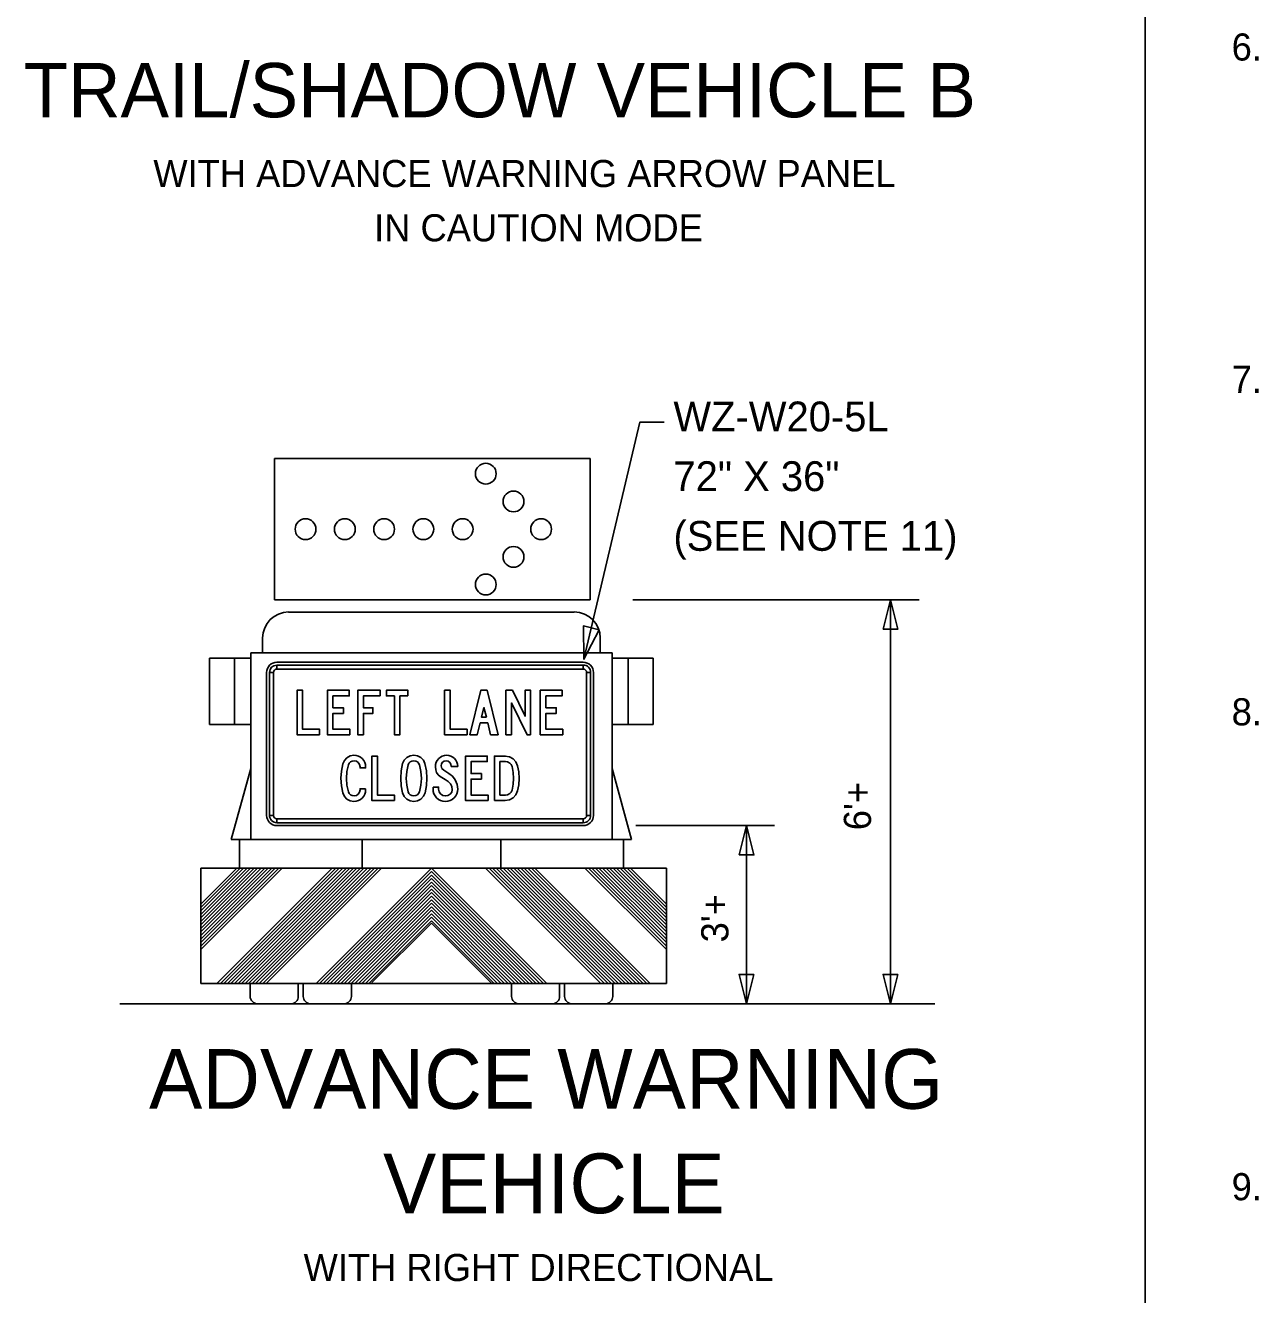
# Model space of a CAD drawing. Extents: x 1374027 to 1374537, y 380415 to 381405.
# Drawn here: x 1374116.56 to 1374143.82, y 381323.05 to 381351.11 of the extents above; entities that cross this region are included whole.
import ezdxf

# ---------------------------------------------------------------- set-up
doc = ezdxf.new("R2010")
doc.units = 0
doc.layers.add('Working Level 1', color=7, linetype='Continuous')

msp = doc.modelspace()

# ---------------------------------------------------------------- linework, layer by layer
at = {"layer": 'Working Level 1'}
for p, q in [((1374141.313, 381402.674), (1374141.313, 381297.674)), ((1374122.066, 381341.535), (1374129.043, 381341.535)), ((1374122.066, 381338.407), (1374122.066, 381341.535)), ((1374129.043, 381338.407), (1374129.043, 381341.535)), ((1374122.066, 381338.407), (1374129.043, 381338.407)), ((1374129.989, 381338.407), (1374136.317, 381338.407)), ((1374135.68, 381329.476), (1374135.68, 381338.407)), ((1374135.68, 381338.407), (1374135.68, 381337.883)), ((1374122.38, 381338.139), (1374128.694, 381338.139)), ((1374121.806, 381337.236), (1374121.806, 381337.566)), ((1374129.268, 381337.236), (1374129.268, 381337.566)), ((1374120.635, 381337.119), (1374121.546, 381337.119)), ((1374120.635, 381335.653), (1374120.635, 381337.119)), ((1374121.187, 381335.653), (1374121.187, 381337.119)), ((1374121.546, 381333.109), (1374121.546, 381337.236)), ((1374121.546, 381337.236), (1374129.529, 381337.236)), ((1374128.892, 381337.029), (1374122.12, 381337.029)), ((1374129.529, 381333.109), (1374129.529, 381337.236)), ((1374130.439, 381337.119), (1374129.529, 381337.119)), ((1374129.888, 381335.653), (1374129.888, 381337.119)), ((1374130.439, 381335.653), (1374130.439, 381337.119)), ((1374121.895, 381336.803), (1374121.895, 381333.643)), ((1374121.957, 381336.803), (1374122.045, 381336.803)), ((1374122.12, 381336.878), (1374122.12, 381336.966)), ((1374128.892, 381336.966), (1374128.892, 381336.878)), ((1374128.967, 381336.803), (1374129.055, 381336.803)), ((1374129.117, 381333.643), (1374129.117, 381336.803)), ((1374120.635, 381335.653), (1374121.546, 381335.653)), ((1374130.439, 381335.653), (1374129.529, 381335.653)), ((1374121.546, 381334.681), (1374121.114, 381333.109)), ((1374129.529, 381334.681), (1374129.96, 381333.109)), ((1374122.045, 381333.643), (1374121.957, 381333.643)), ((1374129.055, 381333.643), (1374128.967, 381333.643)), ((1374122.12, 381333.48), (1374122.12, 381333.568)), ((1374122.12, 381333.417), (1374128.892, 381333.417)), ((1374128.892, 381333.568), (1374128.892, 381333.48)), ((1374130.055, 381333.417), (1374133.116, 381333.417)), ((1374132.499, 381329.476), (1374132.499, 381333.417)), ((1374132.499, 381333.417), (1374132.499, 381332.885)), ((1374121.114, 381333.109), (1374129.96, 381333.109)), ((1374121.293, 381332.479), (1374121.293, 381333.109)), ((1374124.005, 381332.479), (1374124.005, 381333.098)), ((1374127.069, 381332.479), (1374127.069, 381333.098)), ((1374129.781, 381332.479), (1374129.781, 381333.109)), ((1374120.437, 381332.479), (1374130.731, 381332.479)), ((1374120.437, 381332.479), (1374130.731, 381332.479)), ((1374120.437, 381332.479), (1374130.731, 381332.479)), ((1374120.437, 381332.479), (1374130.731, 381332.479)), ((1374120.437, 381329.929), (1374120.437, 381332.479)), ((1374120.437, 381331.681), (1374121.235, 381332.479)), ((1374120.437, 381330.753), (1374122.162, 381332.479)), ((1374120.437, 381330.831), (1374122.084, 381332.479)), ((1374120.437, 381330.909), (1374122.006, 381332.479)), ((1374120.437, 381330.986), (1374121.929, 381332.479)), ((1374120.437, 381331.065), (1374121.851, 381332.479)), ((1374120.437, 381331.143), (1374121.773, 381332.479)), ((1374120.437, 381331.22), (1374121.696, 381332.479)), ((1374120.437, 381331.298), (1374121.618, 381332.479)), ((1374120.437, 381331.376), (1374121.54, 381332.479)), ((1374120.437, 381331.454), (1374121.462, 381332.479)), ((1374120.437, 381331.531), (1374121.385, 381332.479)), ((1374120.437, 381331.609), (1374121.307, 381332.479)), ((1374120.437, 381330.676), (1374122.238, 381332.477)), ((1374120.796, 381329.929), (1374123.345, 381332.479)), ((1374120.873, 381329.929), (1374123.423, 381332.479)), ((1374120.951, 381329.929), (1374123.501, 381332.479)), ((1374121.029, 381329.929), (1374123.579, 381332.479)), ((1374121.106, 381329.929), (1374123.656, 381332.479)), ((1374121.185, 381329.929), (1374123.734, 381332.479)), ((1374121.263, 381329.929), (1374123.812, 381332.479)), ((1374121.341, 381329.929), (1374123.891, 381332.479)), ((1374121.418, 381329.929), (1374123.968, 381332.479)), ((1374121.496, 381329.929), (1374124.046, 381332.479)), ((1374121.574, 381329.929), (1374124.124, 381332.479)), ((1374121.651, 381329.929), (1374124.201, 381332.479)), ((1374121.729, 381329.929), (1374124.279, 381332.479)), ((1374121.807, 381329.929), (1374124.356, 381332.478)), ((1374121.885, 381329.929), (1374124.434, 381332.479)), ((1374122.987, 381329.929), (1374125.537, 381332.479)), ((1374123.065, 381329.929), (1374125.537, 381332.402)), ((1374123.143, 381329.929), (1374125.537, 381332.323)), ((1374123.221, 381329.929), (1374125.537, 381332.245)), ((1374128.087, 381329.929), (1374125.537, 381332.479)), ((1374128.006, 381329.934), (1374125.537, 381332.402)), ((1374127.932, 381329.929), (1374125.537, 381332.323)), ((1374127.854, 381329.929), (1374125.537, 381332.245)), ((1374129.283, 381329.929), (1374126.733, 381332.479)), ((1374129.361, 381329.929), (1374126.812, 381332.478)), ((1374129.439, 381329.929), (1374126.889, 381332.479)), ((1374129.517, 381329.929), (1374126.967, 381332.479)), ((1374129.594, 381329.929), (1374127.044, 381332.479)), ((1374129.672, 381329.929), (1374127.122, 381332.479)), ((1374129.75, 381329.929), (1374127.2, 381332.479)), ((1374129.827, 381329.929), (1374127.277, 381332.479)), ((1374129.905, 381329.929), (1374127.356, 381332.479)), ((1374129.983, 381329.929), (1374127.434, 381332.479)), ((1374130.062, 381329.929), (1374127.512, 381332.479)), ((1374130.139, 381329.929), (1374127.589, 381332.479)), ((1374130.217, 381329.929), (1374127.667, 381332.479)), ((1374130.295, 381329.929), (1374127.745, 381332.479)), ((1374130.372, 381329.929), (1374127.822, 381332.479)), ((1374130.731, 381330.676), (1374128.93, 381332.477)), ((1374130.731, 381330.753), (1374129.006, 381332.479)), ((1374130.731, 381330.831), (1374129.084, 381332.479)), ((1374130.731, 381330.909), (1374129.162, 381332.479)), ((1374130.731, 381330.986), (1374129.239, 381332.479)), ((1374130.731, 381331.065), (1374129.317, 381332.479)), ((1374130.731, 381331.143), (1374129.395, 381332.479)), ((1374130.731, 381331.22), (1374129.472, 381332.479)), ((1374130.731, 381331.298), (1374129.55, 381332.479)), ((1374130.731, 381331.376), (1374129.628, 381332.479)), ((1374130.731, 381331.454), (1374129.706, 381332.479)), ((1374130.731, 381331.531), (1374129.783, 381332.479)), ((1374130.731, 381331.609), (1374129.861, 381332.479)), ((1374130.731, 381331.681), (1374129.933, 381332.479)), ((1374130.731, 381329.929), (1374130.731, 381332.479)), ((1374123.298, 381329.929), (1374125.537, 381332.168)), ((1374123.376, 381329.929), (1374125.537, 381332.09)), ((1374123.454, 381329.929), (1374125.537, 381332.012)), ((1374127.777, 381329.929), (1374125.537, 381332.168)), ((1374127.699, 381329.929), (1374125.537, 381332.09)), ((1374127.621, 381329.929), (1374125.537, 381332.012)), ((1374123.531, 381329.929), (1374125.537, 381331.935)), ((1374123.609, 381329.929), (1374125.537, 381331.857)), ((1374123.688, 381329.929), (1374125.537, 381331.779)), ((1374123.766, 381329.929), (1374125.537, 381331.701)), ((1374127.544, 381329.929), (1374125.537, 381331.935)), ((1374127.466, 381329.929), (1374125.537, 381331.857)), ((1374127.387, 381329.929), (1374125.537, 381331.779)), ((1374127.309, 381329.929), (1374125.537, 381331.701)), ((1374123.843, 381329.929), (1374125.537, 381331.624)), ((1374123.921, 381329.929), (1374125.537, 381331.546)), ((1374123.999, 381329.929), (1374125.537, 381331.468)), ((1374124.076, 381329.929), (1374125.537, 381331.391)), ((1374127.232, 381329.929), (1374125.537, 381331.624)), ((1374127.154, 381329.929), (1374125.537, 381331.546)), ((1374127.076, 381329.929), (1374125.537, 381331.468)), ((1374126.999, 381329.929), (1374125.537, 381331.391)), ((1374124.153, 381329.929), (1374125.537, 381331.313)), ((1374124.219, 381329.944), (1374125.537, 381331.263)), ((1374126.921, 381329.929), (1374125.537, 381331.313)), ((1374126.87, 381329.929), (1374125.537, 381331.263)), ((1374120.437, 381329.929), (1374130.731, 381329.929)), ((1374120.437, 381329.929), (1374130.731, 381329.929)), ((1374120.437, 381329.929), (1374130.731, 381329.929)), ((1374120.437, 381329.929), (1374130.731, 381329.929)), ((1374121.53, 381329.641), (1374121.53, 381329.929)), ((1374122.594, 381329.641), (1374122.594, 381329.929)), ((1374122.704, 381329.641), (1374122.704, 381329.929)), ((1374123.768, 381329.641), (1374123.768, 381329.929)), ((1374127.307, 381329.641), (1374127.307, 381329.929)), ((1374128.37, 381329.641), (1374128.37, 381329.929)), ((1374128.48, 381329.641), (1374128.48, 381329.929)), ((1374129.544, 381329.641), (1374129.544, 381329.929)), ((1374118.649, 381329.476), (1374136.66, 381329.476)), ((1374121.53, 381329.476), (1374122.594, 381329.476)), ((1374121.53, 381329.476), (1374122.594, 381329.476)), ((1374121.53, 381329.476), (1374122.594, 381329.476)), ((1374121.53, 381329.476), (1374122.594, 381329.476)), ((1374122.704, 381329.476), (1374123.768, 381329.476)), ((1374122.704, 381329.476), (1374123.768, 381329.476)), ((1374122.704, 381329.476), (1374123.768, 381329.476)), ((1374122.704, 381329.476), (1374123.768, 381329.476)), ((1374128.37, 381329.476), (1374127.307, 381329.476)), ((1374128.37, 381329.476), (1374127.307, 381329.476)), ((1374128.37, 381329.476), (1374127.307, 381329.476)), ((1374128.37, 381329.476), (1374127.307, 381329.476)), ((1374129.544, 381329.476), (1374128.48, 381329.476)), ((1374129.544, 381329.476), (1374128.48, 381329.476)), ((1374129.544, 381329.476), (1374128.48, 381329.476)), ((1374129.544, 381329.476), (1374128.48, 381329.476))]:
    msp.add_line(p, q, dxfattribs=at)
for points in [[(1374128.906, 381337.094), (1374130.141, 381342.334), (1374130.681, 381342.334)], [(1374127.008, 381335.424), (1374126.767, 381336.409), (1374126.627, 381336.409), (1374126.387, 381335.424), (1374126.55, 381335.424), (1374126.614, 381335.688), (1374126.78, 381335.688), (1374126.844, 381335.424), (1374127.008, 381335.424)], [(1374126.75, 381335.811), (1374126.644, 381335.811), (1374126.697, 381336.028), (1374126.75, 381335.811)], [(1374125.438, 381334.463), (1374125.427, 381334.628), (1374125.394, 381334.788), (1374125.36, 381334.862), (1374125.303, 381334.921), (1374125.23, 381334.959), (1374125.148, 381334.972), (1374125.065, 381334.959), (1374124.992, 381334.92), (1374124.935, 381334.861), (1374124.9, 381334.787), (1374124.868, 381334.627), (1374124.857, 381334.463), (1374124.868, 381334.299), (1374124.9, 381334.139), (1374124.934, 381334.064), (1374124.991, 381334.004), (1374125.065, 381333.965), (1374125.148, 381333.952), (1374125.231, 381333.965), (1374125.304, 381334.004), (1374125.361, 381334.065), (1374125.395, 381334.14), (1374125.427, 381334.3), (1374125.438, 381334.463)], [(1374125.315, 381334.462), (1374125.304, 381334.31), (1374125.272, 381334.161), (1374125.254, 381334.127), (1374125.226, 381334.099), (1374125.189, 381334.081), (1374125.148, 381334.075), (1374125.106, 381334.081), (1374125.069, 381334.1), (1374125.04, 381334.128), (1374125.023, 381334.163), (1374124.991, 381334.311), (1374124.98, 381334.462), (1374124.991, 381334.614), (1374125.023, 381334.763), (1374125.04, 381334.797), (1374125.069, 381334.825), (1374125.106, 381334.843), (1374125.148, 381334.849), (1374125.189, 381334.843), (1374125.226, 381334.825), (1374125.254, 381334.797), (1374125.272, 381334.763), (1374125.304, 381334.615), (1374125.315, 381334.462)], [(1374126.927, 381333.969), (1374127.168, 381333.969), (1374127.261, 381333.984), (1374127.342, 381334.03), (1374127.405, 381334.098), (1374127.441, 381334.183), (1374127.465, 381334.321), (1374127.473, 381334.462), (1374127.465, 381334.603), (1374127.441, 381334.741), (1374127.405, 381334.825), (1374127.342, 381334.894), (1374127.261, 381334.939), (1374127.168, 381334.955), (1374126.927, 381334.955), (1374126.927, 381333.969)], [(1374127.051, 381334.093), (1374127.051, 381334.832), (1374127.171, 381334.832), (1374127.221, 381334.824), (1374127.266, 381334.8), (1374127.3, 381334.765), (1374127.319, 381334.721), (1374127.342, 381334.592), (1374127.35, 381334.462), (1374127.342, 381334.331), (1374127.319, 381334.204), (1374127.3, 381334.159), (1374127.266, 381334.124), (1374127.221, 381334.1), (1374127.171, 381334.093), (1374127.051, 381334.093)]]:
    msp.add_lwpolyline(points, dxfattribs=at)
for points in [[(1374135.518, 381337.757), (1374135.68, 381338.407), (1374135.843, 381337.757)], [(1374129.244, 381337.749), (1374128.906, 381337.094), (1374128.896, 381337.831)], [(1374121.957, 381336.803), (1374121.957, 381333.643), (1374122.045, 381333.643), (1374122.045, 381336.803), (1374121.957, 381336.803)], [(1374128.892, 381336.966), (1374122.12, 381336.966), (1374122.12, 381336.878), (1374128.892, 381336.878), (1374128.892, 381336.966)], [(1374129.055, 381333.643), (1374129.055, 381336.803), (1374128.967, 381336.803), (1374128.967, 381333.643), (1374129.055, 381333.643)], [(1374123.064, 381335.424), (1374123.064, 381335.547), (1374122.69, 381335.547), (1374122.69, 381336.409), (1374122.567, 381336.409), (1374122.567, 381335.424)], [(1374123.735, 381335.424), (1374123.735, 381335.547), (1374123.361, 381335.547), (1374123.361, 381335.899), (1374123.59, 381335.899), (1374123.59, 381336.022), (1374123.361, 381336.022), (1374123.361, 381336.286), (1374123.719, 381336.286), (1374123.719, 381336.409), (1374123.238, 381336.409), (1374123.238, 381335.424)], [(1374124.406, 381336.286), (1374124.406, 381336.409), (1374123.909, 381336.409), (1374123.909, 381335.424), (1374124.032, 381335.424), (1374124.032, 381335.899), (1374124.243, 381335.899), (1374124.243, 381336.022), (1374124.032, 381336.022), (1374124.032, 381336.286)], [(1374125.017, 381336.286), (1374125.017, 381336.409), (1374124.542, 381336.409), (1374124.542, 381336.286), (1374124.718, 381336.286), (1374124.718, 381335.424), (1374124.841, 381335.424), (1374124.841, 381336.286)], [(1374126.325, 381335.424), (1374126.325, 381335.547), (1374125.952, 381335.547), (1374125.952, 381336.409), (1374125.829, 381336.409), (1374125.829, 381335.424)], [(1374127.729, 381335.424), (1374127.729, 381336.409), (1374127.606, 381336.409), (1374127.606, 381335.835), (1374127.326, 381336.409), (1374127.183, 381336.409), (1374127.183, 381335.424), (1374127.306, 381335.424), (1374127.306, 381336.129), (1374127.649, 381335.424)], [(1374128.44, 381335.424), (1374128.44, 381335.547), (1374128.066, 381335.547), (1374128.066, 381335.899), (1374128.295, 381335.899), (1374128.295, 381336.022), (1374128.066, 381336.022), (1374128.066, 381336.286), (1374128.424, 381336.286), (1374128.424, 381336.409), (1374127.943, 381336.409), (1374127.943, 381335.424)], [(1374124.081, 381334.233), (1374123.958, 381334.233), (1374123.958, 381334.205), (1374123.949, 381334.155), (1374123.92, 381334.113), (1374123.877, 381334.084), (1374123.827, 381334.075), (1374123.786, 381334.081), (1374123.748, 381334.1), (1374123.719, 381334.128), (1374123.702, 381334.163), (1374123.67, 381334.31), (1374123.659, 381334.462), (1374123.67, 381334.613), (1374123.702, 381334.76), (1374123.719, 381334.796), (1374123.748, 381334.824), (1374123.786, 381334.843), (1374123.827, 381334.849), (1374123.877, 381334.84), (1374123.92, 381334.811), (1374123.949, 381334.769), (1374123.958, 381334.719), (1374123.958, 381334.691), (1374124.081, 381334.691), (1374124.081, 381334.716), (1374124.077, 381334.767), (1374124.063, 381334.814), (1374124.039, 381334.857), (1374124.007, 381334.897), (1374123.967, 381334.93), (1374123.924, 381334.953), (1374123.876, 381334.967), (1374123.825, 381334.972), (1374123.742, 381334.959), (1374123.669, 381334.919), (1374123.612, 381334.859), (1374123.578, 381334.784), (1374123.546, 381334.624), (1374123.536, 381334.463), (1374123.547, 381334.298), (1374123.579, 381334.139), (1374123.613, 381334.064), (1374123.67, 381334.004), (1374123.743, 381333.965), (1374123.825, 381333.952), (1374123.876, 381333.956), (1374123.924, 381333.97), (1374123.967, 381333.994), (1374124.007, 381334.027), (1374124.039, 381334.066), (1374124.063, 381334.11), (1374124.077, 381334.157), (1374124.081, 381334.208)], [(1374124.717, 381333.969), (1374124.717, 381334.093), (1374124.343, 381334.093), (1374124.343, 381334.955), (1374124.22, 381334.955), (1374124.22, 381333.969)], [(1374125.573, 381334.268), (1374125.573, 381334.228), (1374125.578, 381334.173), (1374125.592, 381334.122), (1374125.617, 381334.075), (1374125.652, 381334.033), (1374125.694, 381333.997), (1374125.74, 381333.972), (1374125.79, 381333.957), (1374125.845, 381333.952), (1374125.9, 381333.957), (1374125.95, 381333.971), (1374125.996, 381333.997), (1374126.038, 381334.032), (1374126.073, 381334.074), (1374126.098, 381334.12), (1374126.113, 381334.17), (1374126.118, 381334.224), (1374126.104, 381334.329), (1374126.063, 381334.427), (1374126, 381334.508), (1374125.918, 381334.572), (1374125.811, 381334.639), (1374125.764, 381334.68), (1374125.749, 381334.736), (1374125.757, 381334.779), (1374125.782, 381334.816), (1374125.818, 381334.841), (1374125.861, 381334.849), (1374125.904, 381334.84), (1374125.94, 381334.813), (1374125.965, 381334.773), (1374125.973, 381334.726), (1374126.118, 381334.726), (1374126.114, 381334.775), (1374126.1, 381334.82), (1374126.077, 381334.862), (1374126.046, 381334.9), (1374126.007, 381334.931), (1374125.966, 381334.954), (1374125.92, 381334.968), (1374125.872, 381334.972), (1374125.822, 381334.968), (1374125.777, 381334.954), (1374125.735, 381334.93), (1374125.697, 381334.898), (1374125.666, 381334.859), (1374125.643, 381334.816), (1374125.63, 381334.769), (1374125.625, 381334.719), (1374125.632, 381334.651), (1374125.652, 381334.592), (1374125.684, 381334.542), (1374125.73, 381334.501), (1374125.838, 381334.436), (1374125.906, 381334.392), (1374125.956, 381334.34), (1374125.985, 381334.278), (1374125.995, 381334.208), (1374125.984, 381334.157), (1374125.951, 381334.114), (1374125.902, 381334.084), (1374125.845, 381334.075), (1374125.787, 381334.086), (1374125.739, 381334.119), (1374125.707, 381334.167), (1374125.696, 381334.224), (1374125.696, 381334.268)], [(1374126.787, 381333.969), (1374126.787, 381334.093), (1374126.413, 381334.093), (1374126.413, 381334.444), (1374126.642, 381334.444), (1374126.642, 381334.568), (1374126.413, 381334.568), (1374126.413, 381334.832), (1374126.771, 381334.832), (1374126.771, 381334.955), (1374126.29, 381334.955), (1374126.29, 381333.969)], [(1374122.12, 381333.48), (1374128.892, 381333.48), (1374128.892, 381333.568), (1374122.12, 381333.568), (1374122.12, 381333.48)], [(1374132.337, 381332.767), (1374132.499, 381333.417), (1374132.662, 381332.767)], [(1374132.662, 381330.126), (1374132.499, 381329.476), (1374132.337, 381330.126)], [(1374135.843, 381330.126), (1374135.68, 381329.476), (1374135.518, 381330.126)]]:
    msp.add_lwpolyline(points, close=True, dxfattribs=at)
for centre, radius, start, end in [((1374126.738, 381341.198), 0.23, 0, 180), ((1374126.738, 381341.198), 0.23, 180, 0), ((1374127.35, 381340.584), 0.23, 0, 180), ((1374127.35, 381340.584), 0.23, 180, 0), ((1374122.754, 381339.971), 0.23, 0, 180), ((1374123.622, 381339.971), 0.23, 0, 180), ((1374124.49, 381339.971), 0.23, 0, 180), ((1374125.358, 381339.971), 0.23, 0, 180), ((1374126.226, 381339.971), 0.23, 0, 180), ((1374127.961, 381339.971), 0.23, 0, 180), ((1374122.754, 381339.971), 0.23, 180, 0), ((1374123.622, 381339.971), 0.23, 180, 0), ((1374124.49, 381339.971), 0.23, 180, 0), ((1374125.358, 381339.971), 0.23, 180, 0), ((1374126.226, 381339.971), 0.23, 180, 0), ((1374127.961, 381339.971), 0.23, 180, 0), ((1374127.35, 381339.359), 0.23, 0, 180), ((1374127.35, 381339.359), 0.23, 180, 0), ((1374126.738, 381338.748), 0.23, 0, 180), ((1374126.738, 381338.748), 0.23, 180, 0), ((1374122.38, 381337.566), 0.574, 90, 180), ((1374128.694, 381337.566), 0.574, 0, 90), ((1374122.12, 381336.803), 0.226, 90.0002, 179.9998), ((1374128.892, 381336.803), 0.226, 0, 90.0002), ((1374122.12, 381336.803), 0.163, 90.0002, 179.9998), ((1374122.12, 381336.803), 0.0752, 90.0002, 179.9998), ((1374128.892, 381336.803), 0.163, 0, 90.0002), ((1374128.892, 381336.803), 0.0752, 0, 90.0002), ((1374122.12, 381333.643), 0.226, 179.9998, 270.0001), ((1374122.12, 381333.643), 0.163, 179.9998, 270.0001), ((1374122.12, 381333.643), 0.0752, 179.9998, 270.0001), ((1374128.892, 381333.643), 0.226, 270.0001, 0.0003), ((1374128.892, 381333.643), 0.163, 270.0001, 0.0003), ((1374128.892, 381333.643), 0.0752, 270.0001, 0.0003), ((1374121.695, 381329.641), 0.165, 180, 270), ((1374122.429, 381329.641), 0.165, 270, 0), ((1374122.869, 381329.641), 0.165, 180, 270), ((1374123.603, 381329.641), 0.165, 270, 0), ((1374127.472, 381329.641), 0.165, 180, 270), ((1374128.205, 381329.641), 0.165, 270, 0), ((1374128.645, 381329.641), 0.165, 180, 270), ((1374129.379, 381329.641), 0.165, 270, 0)]:
    msp.add_arc(centre, radius, start, end, dxfattribs=at)

# ---------------------------------------------------------------- texts
for s, height, p in [('6. ', 0.6, (1374143.222, 381350.333)), ('TRAIL/SHADOW VEHICLE B', 1.2, (1374116.527, 381349.079)), ('WITH ADVANCE WARNING ARROW PANEL', 0.6, (1374119.39, 381347.535)), ('IN CAUTION MODE', 0.6, (1374124.27, 381346.335)), ('7. ', 0.6, (1374143.222, 381342.983)), ('WZ-W20-5L', 0.66, (1374130.885, 381342.133)), ('72" X 36"', 0.66, (1374130.885, 381340.813)), ('(SEE NOTE 11)', 0.66, (1374130.885, 381339.493)), ('8.', 0.6, (1374143.222, 381335.633)), ('ADVANCE WARNING', 1.32, (1374119.295, 381327.156)), ('VEHICLE ', 1.32, (1374124.466, 381324.846)), ('9.', 0.6, (1374143.222, 381325.133)), ('WITH RIGHT DIRECTIONAL', 0.6, (1374122.711, 381323.346))]:
    msp.add_text(s, height=height, dxfattribs=at).set_placement(p)
for s, p in [("6'+", (1374135.251, 381333.315)), ("3'+", (1374132.1, 381330.835))]:
    msp.add_text(s, height=0.6, rotation=90, dxfattribs=at).set_placement(p)

doc.saveas('drawing.dxf')
